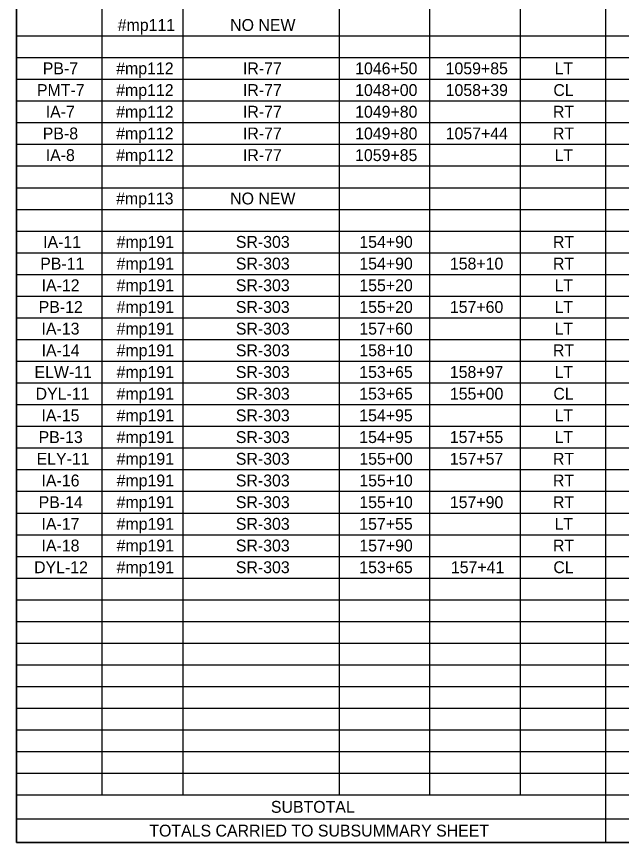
# Model space of a CAD drawing. Extents: x 91011267 to 91022583, y 37007614 to 37014266.
# Drawn here: x 91011277 to 91011661, y 37010175 to 37010699 of the extents above; entities that cross this region are included whole.
import ezdxf

# ---------------------------------------------------------------- set-up
doc = ezdxf.new("R2010")
doc.units = 0
doc.layers.add('SC_Scratch2', color=7, linetype='Continuous')
doc.layers.add('SH_Data', color=7, linetype='Continuous')

msp = doc.modelspace()

# ---------------------------------------------------------------- linework, layer by layer
at = {"layer": 'SC_Scratch2'}
msp.add_lwpolyline([(91011277.35, 37011225.45), (91012802.35, 37011225.45), (91012802.35, 37010175.45), (91011277.35, 37010175.45)], close=True, dxfattribs=at)
at = {"layer": 'SH_Data'}
for p, q in [((91011277.35, 37010851.25), (91011277.35, 37010645.17)), ((91011331.39, 37010851.25), (91011331.39, 37010645.17)), ((91011382.8, 37010851.25), (91011382.8, 37010645.17)), ((91011481.65, 37010851.25), (91011481.65, 37010645.17)), ((91011538.99, 37010851.25), (91011538.99, 37010645.17)), ((91011596.32, 37010851.25), (91011596.32, 37010645.17)), ((91011650.36, 37010851.25), (91011650.36, 37010645.17)), ((91011277.35, 37010686.39), (91011596.32, 37010686.39)), ((91011596.32, 37010686.39), (91011650.36, 37010686.39)), ((91011650.36, 37010686.39), (91011950.88, 37010686.39)), ((91011277.35, 37010672.65), (91011596.32, 37010672.65)), ((91011596.32, 37010672.65), (91011650.36, 37010672.65)), ((91011650.36, 37010672.65), (91011950.88, 37010672.65)), ((91011277.35, 37010658.91), (91011596.32, 37010658.91)), ((91011596.32, 37010658.91), (91011650.36, 37010658.91)), ((91011650.36, 37010658.91), (91011950.88, 37010658.91)), ((91011277.35, 37010645.17), (91011596.32, 37010645.17)), ((91011277.35, 37010645.17), (91011277.35, 37010631.43)), ((91011331.39, 37010645.17), (91011331.39, 37010631.43)), ((91011382.8, 37010645.17), (91011382.8, 37010631.43)), ((91011481.65, 37010645.17), (91011481.65, 37010631.43)), ((91011538.99, 37010645.17), (91011538.99, 37010631.43)), ((91011596.32, 37010645.17), (91011650.36, 37010645.17)), ((91011596.32, 37010645.17), (91011596.32, 37010631.43)), ((91011650.36, 37010645.17), (91011950.88, 37010645.17)), ((91011650.36, 37010645.17), (91011650.36, 37010631.43)), ((91011277.35, 37010631.43), (91011596.32, 37010631.43)), ((91011277.35, 37010631.43), (91011277.35, 37010617.7)), ((91011331.39, 37010631.43), (91011331.39, 37010617.7)), ((91011382.8, 37010631.43), (91011382.8, 37010617.7)), ((91011481.65, 37010631.43), (91011481.65, 37010617.7)), ((91011538.99, 37010631.43), (91011538.99, 37010617.7)), ((91011596.32, 37010631.43), (91011650.36, 37010631.43)), ((91011596.32, 37010631.43), (91011596.32, 37010617.7)), ((91011650.36, 37010631.43), (91011950.88, 37010631.43)), ((91011650.36, 37010631.43), (91011650.36, 37010617.7)), ((91011277.35, 37010617.7), (91011596.32, 37010617.7)), ((91011277.35, 37010617.7), (91011277.35, 37010576.48)), ((91011331.39, 37010617.7), (91011331.39, 37010576.48)), ((91011382.8, 37010617.7), (91011382.8, 37010576.48)), ((91011481.65, 37010617.7), (91011481.65, 37010576.48)), ((91011538.99, 37010617.7), (91011538.99, 37010576.48)), ((91011596.32, 37010617.7), (91011650.36, 37010617.7)), ((91011596.32, 37010617.7), (91011596.32, 37010576.48)), ((91011650.36, 37010617.7), (91011950.88, 37010617.7)), ((91011650.36, 37010617.7), (91011650.36, 37010576.48)), ((91011277.35, 37010603.96), (91011596.32, 37010603.96)), ((91011596.32, 37010603.96), (91011650.36, 37010603.96)), ((91011650.36, 37010603.96), (91011950.88, 37010603.96)), ((91011277.35, 37010590.22), (91011596.32, 37010590.22)), ((91011596.32, 37010590.22), (91011650.36, 37010590.22)), ((91011650.36, 37010590.22), (91011950.88, 37010590.22)), ((91011277.35, 37010576.48), (91011596.32, 37010576.48)), ((91011277.35, 37010576.48), (91011277.35, 37010562.74)), ((91011331.39, 37010576.48), (91011331.39, 37010562.74)), ((91011382.8, 37010576.48), (91011382.8, 37010562.74)), ((91011481.65, 37010576.48), (91011481.65, 37010562.74)), ((91011538.99, 37010576.48), (91011538.99, 37010562.74)), ((91011596.32, 37010576.48), (91011650.36, 37010576.48)), ((91011596.32, 37010576.48), (91011596.32, 37010562.74)), ((91011650.36, 37010576.48), (91011950.88, 37010576.48)), ((91011650.36, 37010576.48), (91011650.36, 37010562.74)), ((91011277.35, 37010562.74), (91011596.32, 37010562.74)), ((91011277.35, 37010562.74), (91011277.35, 37010549)), ((91011331.39, 37010562.74), (91011331.39, 37010549)), ((91011382.8, 37010562.74), (91011382.8, 37010549)), ((91011481.65, 37010562.74), (91011481.65, 37010549)), ((91011538.99, 37010562.74), (91011538.99, 37010549)), ((91011596.32, 37010562.74), (91011650.36, 37010562.74)), ((91011596.32, 37010562.74), (91011596.32, 37010549)), ((91011650.36, 37010562.74), (91011950.88, 37010562.74)), ((91011650.36, 37010562.74), (91011650.36, 37010549)), ((91011277.35, 37010549), (91011596.32, 37010549)), ((91011277.35, 37010549), (91011277.35, 37010507.79)), ((91011331.39, 37010549), (91011331.39, 37010507.79)), ((91011382.8, 37010549), (91011382.8, 37010507.79)), ((91011481.65, 37010549), (91011481.65, 37010507.79)), ((91011538.99, 37010549), (91011538.99, 37010507.79)), ((91011596.32, 37010549), (91011650.36, 37010549)), ((91011596.32, 37010549), (91011596.32, 37010507.79)), ((91011650.36, 37010549), (91011950.88, 37010549)), ((91011650.36, 37010549), (91011650.36, 37010507.79)), ((91011277.35, 37010535.27), (91011596.32, 37010535.27)), ((91011596.32, 37010535.27), (91011650.36, 37010535.27)), ((91011650.36, 37010535.27), (91011950.88, 37010535.27)), ((91011277.35, 37010521.53), (91011596.32, 37010521.53)), ((91011596.32, 37010521.53), (91011650.36, 37010521.53)), ((91011650.36, 37010521.53), (91011950.88, 37010521.53)), ((91011277.35, 37010507.79), (91011596.32, 37010507.79)), ((91011277.35, 37010507.79), (91011277.35, 37010494.05)), ((91011331.39, 37010507.79), (91011331.39, 37010494.05)), ((91011382.8, 37010507.79), (91011382.8, 37010494.05)), ((91011481.65, 37010507.79), (91011481.65, 37010494.05)), ((91011538.99, 37010507.79), (91011538.99, 37010494.05)), ((91011596.32, 37010507.79), (91011650.36, 37010507.79)), ((91011596.32, 37010507.79), (91011596.32, 37010494.05)), ((91011650.36, 37010507.79), (91011950.88, 37010507.79)), ((91011650.36, 37010507.79), (91011650.36, 37010494.05)), ((91011277.35, 37010494.05), (91011596.32, 37010494.05)), ((91011277.35, 37010494.05), (91011277.35, 37010480.31)), ((91011331.39, 37010494.05), (91011331.39, 37010480.31)), ((91011382.8, 37010494.05), (91011382.8, 37010480.31)), ((91011481.65, 37010494.05), (91011481.65, 37010480.31)), ((91011538.99, 37010494.05), (91011538.99, 37010480.31)), ((91011596.32, 37010494.05), (91011650.36, 37010494.05)), ((91011596.32, 37010494.05), (91011596.32, 37010480.31)), ((91011650.36, 37010494.05), (91011950.88, 37010494.05)), ((91011650.36, 37010494.05), (91011650.36, 37010480.31)), ((91011277.35, 37010480.31), (91011596.32, 37010480.31)), ((91011277.35, 37010480.31), (91011277.35, 37010175.45)), ((91011331.39, 37010480.31), (91011331.39, 37010205.55)), ((91011382.8, 37010480.31), (91011382.8, 37010205.55)), ((91011481.65, 37010480.31), (91011481.65, 37010205.55)), ((91011538.99, 37010480.31), (91011538.99, 37010205.55)), ((91011596.32, 37010480.31), (91011650.36, 37010480.31)), ((91011596.32, 37010480.31), (91011596.32, 37010205.55)), ((91011650.36, 37010480.31), (91011950.88, 37010480.31)), ((91011650.36, 37010480.31), (91011650.36, 37010175.45)), ((91011277.35, 37010466.57), (91011596.32, 37010466.57)), ((91011596.32, 37010466.57), (91011650.36, 37010466.57)), ((91011650.36, 37010466.57), (91011950.88, 37010466.57)), ((91011277.35, 37010452.84), (91011596.32, 37010452.84)), ((91011596.32, 37010452.84), (91011650.36, 37010452.84)), ((91011650.36, 37010452.84), (91011950.88, 37010452.84)), ((91011277.35, 37010439.1), (91011596.32, 37010439.1)), ((91011596.32, 37010439.1), (91011650.36, 37010439.1)), ((91011650.36, 37010439.1), (91011950.88, 37010439.1)), ((91011277.35, 37010425.36), (91011596.32, 37010425.36)), ((91011596.32, 37010425.36), (91011650.36, 37010425.36)), ((91011650.36, 37010425.36), (91011950.88, 37010425.36)), ((91011277.35, 37010411.62), (91011596.32, 37010411.62)), ((91011596.32, 37010411.62), (91011650.36, 37010411.62)), ((91011650.36, 37010411.62), (91011950.88, 37010411.62)), ((91011277.35, 37010397.88), (91011596.32, 37010397.88)), ((91011596.32, 37010397.88), (91011650.36, 37010397.88)), ((91011650.36, 37010397.88), (91011950.88, 37010397.88)), ((91011277.35, 37010384.14), (91011596.32, 37010384.14)), ((91011596.32, 37010384.14), (91011650.36, 37010384.14)), ((91011650.36, 37010384.14), (91011950.88, 37010384.14)), ((91011277.35, 37010370.41), (91011596.32, 37010370.41)), ((91011596.32, 37010370.41), (91011650.36, 37010370.41)), ((91011650.36, 37010370.41), (91011950.88, 37010370.41)), ((91011277.35, 37010356.67), (91011596.32, 37010356.67)), ((91011596.32, 37010356.67), (91011650.36, 37010356.67)), ((91011650.36, 37010356.67), (91011950.88, 37010356.67)), ((91011277.35, 37010342.93), (91011596.32, 37010342.93)), ((91011596.32, 37010342.93), (91011650.36, 37010342.93)), ((91011650.36, 37010342.93), (91011950.88, 37010342.93)), ((91011277.35, 37010329.19), (91011596.32, 37010329.19)), ((91011596.32, 37010329.19), (91011650.36, 37010329.19)), ((91011650.36, 37010329.19), (91011950.88, 37010329.19)), ((91011277.35, 37010315.45), (91011596.32, 37010315.45)), ((91011596.32, 37010315.45), (91011650.36, 37010315.45)), ((91011650.36, 37010315.45), (91011950.88, 37010315.45)), ((91011277.35, 37010301.71), (91011596.32, 37010301.71)), ((91011596.32, 37010301.71), (91011650.36, 37010301.71)), ((91011650.36, 37010301.71), (91011950.88, 37010301.71)), ((91011277.35, 37010287.98), (91011596.32, 37010287.98)), ((91011596.32, 37010287.98), (91011650.36, 37010287.98)), ((91011650.36, 37010287.98), (91011950.88, 37010287.98)), ((91011277.35, 37010274.24), (91011596.32, 37010274.24)), ((91011596.32, 37010274.24), (91011650.36, 37010274.24)), ((91011650.36, 37010274.24), (91011950.88, 37010274.24)), ((91011277.35, 37010260.5), (91011596.32, 37010260.5)), ((91011596.32, 37010260.5), (91011650.36, 37010260.5)), ((91011650.36, 37010260.5), (91011950.88, 37010260.5)), ((91011277.35, 37010246.76), (91011596.32, 37010246.76)), ((91011596.32, 37010246.76), (91011650.36, 37010246.76)), ((91011650.36, 37010246.76), (91011950.88, 37010246.76)), ((91011277.35, 37010233.02), (91011596.32, 37010233.02)), ((91011596.32, 37010233.02), (91011650.36, 37010233.02)), ((91011650.36, 37010233.02), (91011950.88, 37010233.02)), ((91011277.35, 37010219.29), (91011596.32, 37010219.29)), ((91011596.32, 37010219.29), (91011650.36, 37010219.29)), ((91011650.36, 37010219.29), (91011950.88, 37010219.29)), ((91011277.35, 37010205.55), (91011596.32, 37010205.55)), ((91011596.32, 37010205.55), (91011650.36, 37010205.55)), ((91011650.36, 37010205.55), (91011950.88, 37010205.55)), ((91011277.35, 37010190.5), (91011596.32, 37010190.5)), ((91011596.32, 37010190.5), (91011650.36, 37010190.5)), ((91011650.36, 37010190.5), (91011950.88, 37010190.5)), ((91011277.35, 37010175.45), (91011596.32, 37010175.45)), ((91011596.32, 37010175.45), (91011650.36, 37010175.45)), ((91011650.36, 37010175.45), (91011950.88, 37010175.45))]:
    msp.add_line(p, q, dxfattribs=at)

# ---------------------------------------------------------------- texts
for s, height, p in [('NO NEW', 7.523, (91011412.69, 37010689.5)), ('#mp111', 7.523, (91011341.46, 37010689.5)), ('PB-7', 7.523, (91011293.99, 37010662.02)), ('#mp112', 7.523, (91011340.49, 37010662.02)), ('IR-77', 7.523, (91011420.79, 37010662.02)), ('1046+50', 7.523, (91011491.87, 37010662.02)), ('1059+85', 7.523, (91011549.17, 37010662.02)), ('LT', 7.523, (91011618.23, 37010662.02)), ('PMT-7', 7.523, (91011290.29, 37010648.28)), ('#mp112', 7.523, (91011340.49, 37010648.28)), ('IR-77', 7.523, (91011420.79, 37010648.28)), ('1048+00', 7.523, (91011491.87, 37010648.28)), ('1058+39', 7.523, (91011549.19, 37010648.28)), ('CL', 7.523, (91011617.42, 37010648.28)), ('IA-7', 7.523, (91011295.85, 37010634.54)), ('#mp112', 7.523, (91011340.49, 37010634.54)), ('IR-77', 7.523, (91011420.79, 37010634.54)), ('1049+80', 7.523, (91011491.87, 37010634.54)), ('RT', 7.523, (91011617.17, 37010634.54)), ('PB-8', 7.523, (91011293.99, 37010620.8)), ('#mp112', 7.523, (91011340.49, 37010620.8)), ('IR-77', 7.523, (91011420.79, 37010620.8)), ('1049+80', 7.523, (91011491.87, 37010620.8)), ('1057+44', 7.523, (91011549.21, 37010620.8)), ('RT', 7.523, (91011617.17, 37010620.8)), ('IA-8', 7.523, (91011295.84, 37010607.07)), ('#mp112', 7.523, (91011340.49, 37010607.07)), ('IR-77', 7.523, (91011420.79, 37010607.07)), ('1059+85', 7.523, (91011491.83, 37010607.07)), ('LT', 7.523, (91011618.23, 37010607.07)), ('#mp113', 7.523, (91011340.45, 37010579.59)), ('NO NEW', 7.523, (91011412.69, 37010579.59)), ('IA-11', 7.523, (91011294.21, 37010552.11)), ('#mp191', 7.523, (91011340.76, 37010552.11)), ('SR-303', 7.523, (91011416.29, 37010552.11)), ('154+90', 7.523, (91011494.52, 37010552.11)), ('RT', 7.523, (91011617.17, 37010552.11)), ('PB-11', 7.523, (91011292.36, 37010538.37)), ('#mp191', 7.523, (91011340.76, 37010538.37)), ('SR-303', 7.523, (91011416.29, 37010538.37)), ('154+90', 7.523, (91011494.52, 37010538.37)), ('158+10', 7.523, (91011551.86, 37010538.37)), ('RT', 7.523, (91011617.17, 37010538.37)), ('IA-12', 7.523, (91011293.24, 37010524.64)), ('#mp191', 7.523, (91011340.76, 37010524.64)), ('SR-303', 7.523, (91011416.29, 37010524.64)), ('155+20', 7.523, (91011494.52, 37010524.64)), ('LT', 7.523, (91011618.23, 37010524.64)), ('PB-12', 7.523, (91011291.38, 37010510.9)), ('#mp191', 7.523, (91011340.76, 37010510.9)), ('SR-303', 7.523, (91011416.29, 37010510.9)), ('155+20', 7.523, (91011494.52, 37010510.9)), ('157+60', 7.523, (91011551.86, 37010510.9)), ('LT', 7.523, (91011618.23, 37010510.9)), ('IA-13', 7.523, (91011293.2, 37010497.16)), ('#mp191', 7.523, (91011340.76, 37010497.16)), ('SR-303', 7.523, (91011416.29, 37010497.16)), ('157+60', 7.523, (91011494.52, 37010497.16)), ('LT', 7.523, (91011618.23, 37010497.16)), ('IA-14', 7.523, (91011293.22, 37010483.42)), ('#mp191', 7.523, (91011340.76, 37010483.42)), ('SR-303', 7.523, (91011416.29, 37010483.42)), ('158+10', 7.523, (91011494.52, 37010483.42)), ('RT', 7.523, (91011617.17, 37010483.42)), ('ELW-11', 7.523, (91011288.75, 37010469.68)), ('#mp191', 7.523, (91011340.76, 37010469.68)), ('SR-303', 7.523, (91011416.29, 37010469.68)), ('153+65', 7.523, (91011494.48, 37010469.68)), ('158+97', 7.523, (91011551.84, 37010469.68)), ('LT', 7.523, (91011618.23, 37010469.68)), ('DYL-11', 7.523, (91011289.45, 37010455.94)), ('#mp191', 7.523, (91011340.76, 37010455.94)), ('SR-303', 7.523, (91011416.29, 37010455.94)), ('153+65', 7.523, (91011494.48, 37010455.94)), ('155+00', 7.523, (91011551.86, 37010455.94)), ('CL', 7.523, (91011617.42, 37010455.94)), ('IA-15', 7.523, (91011293.17, 37010442.21)), ('#mp191', 7.523, (91011340.76, 37010442.21)), ('SR-303', 7.523, (91011416.29, 37010442.21)), ('154+95', 7.523, (91011494.48, 37010442.21)), ('LT', 7.523, (91011618.23, 37010442.21)), ('PB-13', 7.523, (91011291.34, 37010428.47)), ('#mp191', 7.523, (91011340.76, 37010428.47)), ('SR-303', 7.523, (91011416.29, 37010428.47)), ('154+95', 7.523, (91011494.48, 37010428.47)), ('157+55', 7.523, (91011551.82, 37010428.47)), ('LT', 7.523, (91011618.23, 37010428.47)), ('ELY-11', 7.523, (91011290.06, 37010414.73)), ('#mp191', 7.523, (91011340.76, 37010414.73)), ('SR-303', 7.523, (91011416.29, 37010414.73)), ('155+00', 7.523, (91011494.52, 37010414.73)), ('157+57', 7.523, (91011551.84, 37010414.73)), ('RT', 7.523, (91011617.17, 37010414.73)), ('IA-16', 7.523, (91011293.2, 37010400.99)), ('#mp191', 7.523, (91011340.76, 37010400.99)), ('SR-303', 7.523, (91011416.29, 37010400.99)), ('155+10', 7.523, (91011494.52, 37010400.99)), ('RT', 7.523, (91011617.17, 37010400.99)), ('PB-14', 7.523, (91011291.36, 37010387.25)), ('#mp191', 7.523, (91011340.76, 37010387.25)), ('SR-303', 7.523, (91011416.29, 37010387.25)), ('155+10', 7.523, (91011494.52, 37010387.25)), ('157+90', 7.523, (91011551.86, 37010387.25)), ('RT', 7.523, (91011617.17, 37010387.25)), ('IA-17', 7.523, (91011293.2, 37010373.51)), ('#mp191', 7.523, (91011340.76, 37010373.51)), ('SR-303', 7.523, (91011416.29, 37010373.51)), ('157+55', 7.523, (91011494.48, 37010373.51)), ('LT', 7.523, (91011618.23, 37010373.51)), ('IA-18', 7.523, (91011293.2, 37010359.78)), ('#mp191', 7.523, (91011340.76, 37010359.78)), ('SR-303', 7.523, (91011416.29, 37010359.78)), ('157+90', 7.523, (91011494.52, 37010359.78)), ('RT', 7.523, (91011617.17, 37010359.78)), ('DYL-12', 7.523, (91011288.47, 37010346.04)), ('#mp191', 7.523, (91011340.76, 37010346.04)), ('SR-303', 7.523, (91011416.29, 37010346.04)), ('153+65', 7.523, (91011494.48, 37010346.04)), ('157+41', 7.523, (91011552.5, 37010346.04)), ('CL', 7.523, (91011617.42, 37010346.04)), ('SUBTOTAL', 7.523, (91011438.49, 37010194.26)), ('TOTALS CARRIED TO SUBSUMMARY SHEET', 7.5234, (91011361.48, 37010179.21))]:
    msp.add_text(s, height=height, dxfattribs=at).set_placement(p)

doc.saveas('drawing.dxf')
